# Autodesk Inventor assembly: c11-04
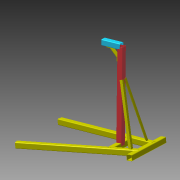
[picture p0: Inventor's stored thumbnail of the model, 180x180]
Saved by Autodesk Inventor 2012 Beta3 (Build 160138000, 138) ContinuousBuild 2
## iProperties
Created: 2011-01
Part Number: c11-04
Document SubType Name: Assembly
Designer: Beta-8540w
_SolveAssemblyDoc: Frame Generator Solve Assembly
_Version: 15.0.0
Author: Beta-8540w
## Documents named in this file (3)
- C:\Inventor 2012 Essentials\Assemblies\Chapter 11\c11-04.iam
- C:\Inventor 2012 Essentials\Parts\Chapter 11\c11-01.ipt
- C:\Inventor 2012 Essentials\Assemblies\Chapter 11\Frame\Frame c11-04.iam
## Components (2 placed, 2 different names)
1. c11-01:1
2. Frame c11-04:1 [sub-assembly]
